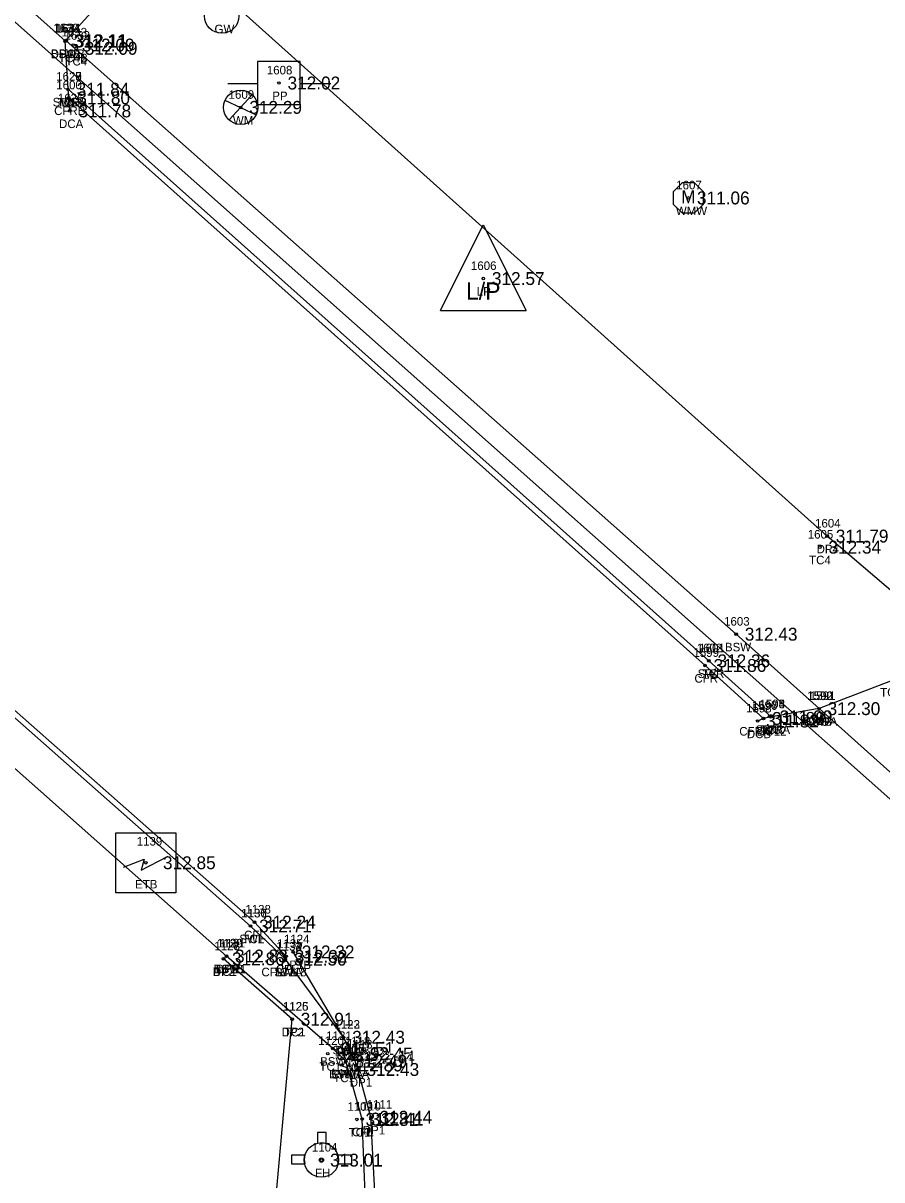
# Model space of a CAD drawing. Extents: x 1970076 to 1971136, y 803126 to 804215.
# Drawn here: x 1970842 to 1970942, y 803243.6 to 803378.3 of the extents above; entities that cross this region are included whole.
import ezdxf

# ---------------------------------------------------------------- set-up
doc = ezdxf.new("R2010")
doc.units = 0
for name, color, linetype in [('RD_EX_Conc', 7, 'Continuous'), ('RD_EX_Conc_txCode', 7, 'Continuous'), ('RD_EX_DR_Pipe', 7, 'Continuous'), ('RD_EX_Driveway', 7, 'Continuous'), ('RD_EX_Driveway_txCode', 7, 'Continuous'), ('RD_EX_Misc_txCode', 7, 'Continuous'), ('RD_EX_SU_H2O', 7, 'Continuous'), ('RD_EX_TX_Conc_ELEV', 7, 'Continuous'), ('RD_EX_TX_Driveway_ELEV', 7, 'Continuous'), ('RD_EX_TX_Misc_ELEV', 7, 'Continuous'), ('RD_EX_TX_UT_ELEV', 7, 'Continuous'), ('RD_EX_UT', 7, 'Continuous'), ('RD_EX_UT_txCode', 7, 'Continuous'), ('RD_HC_Survey_ELEV', 7, 'Continuous'), ('RD_SMD_Locator', 7, 'Continuous')]:
    doc.layers.add(name, color=color, linetype=linetype)

msp = doc.modelspace()

# ---------------------------------------------------------------- linework, layer by layer
at = {"layer": 'RD_EX_Conc'}
for points in [[(1970847.44, 803368.09), (1970847.23, 803370.61), (1970846.91, 803376.25), (1970825.43, 803395.36), (1970822.14, 803392.47), (1970821.14, 803392.59), (1970820.38, 803392.03)], [(1970934.65, 803298.46), (1970925.01, 803307.13), (1970847.03, 803376.25)], [(1970929.07, 803297.51), (1970921.83, 803304.03), (1970847.23, 803370.61)], [(1970928.19, 803297.32), (1970921.38, 803303.49), (1970847.31, 803369.61)], [(1970879.58, 803257.38), (1970880.21, 803258.23), (1970879.31, 803260.18), (1970872.53, 803269.28), (1970868.47, 803273.14), (1970819.57, 803316.35), (1970792.83, 803340.24), (1970791.56, 803341.26)], [(1970872.53, 803269.28), (1970872.62, 803269.6), (1970868.93, 803273.59), (1970819.97, 803316.84), (1970793.14, 803340.78), (1970791.95, 803341.72)], [(1970879.58, 803257.38), (1970878.06, 803258.86), (1970865.67, 803269.64), (1970816.24, 803313.45), (1970789.11, 803337.91)], [(1971009.74, 803224.24), (1971010.01, 803224.85), (1971010.25, 803225.52), (1971006.59, 803233.99), (1970934.65, 803298.46), (1970929.07, 803297.51), (1970928.19, 803297.32), (1970927.5, 803297.02)], [(1970854.49, 803199.55), (1970873.43, 803218.79), (1970878.63, 803227.37), (1970881.85, 803240.99), (1970881.47, 803250.65), (1970879.58, 803257.38)]]:
    msp.add_lwpolyline(points, dxfattribs=at)
at = {"layer": 'RD_EX_DR_Pipe'}
msp.add_line((1971022.85, 803216.85), (1970817.34, 803399.52), dxfattribs=at)
at = {"layer": 'RD_EX_Driveway'}
for points in [[(1970978.49, 803349.37), (1970974.36, 803344.54), (1970973.43, 803342.01), (1970974.82, 803339.34), (1970978.6, 803335.88), (1970962.13, 803321.3), (1970960.21, 803322.85), (1970957.7, 803323.38), (1970955.12, 803322.32), (1970943.79, 803311.55), (1970935.6, 803318.56), (1970864.97, 803381.97), (1970876.89, 803395.59), (1970878.3, 803398.67), (1970875.35, 803402.77), (1970871.74, 803402.91), (1970869.45, 803401.14), (1970846.9, 803376.22)], [(1970991.2, 803336.74), (1970966.5, 803314.66), (1970943.49, 803301.87), (1970934.65, 803298.46)], [(1970853.81, 803200.3), (1970867.75, 803214.13), (1970871.37, 803240.87), (1970873.32, 803262.28), (1970865.32, 803269.32), (1970865.67, 803269.64), (1970816.24, 803313.45)], [(1970855.26, 803198.86), (1970874.18, 803218.16), (1970879.6, 803226.99), (1970883.03, 803240.73), (1970882.49, 803250.86), (1970880.97, 803256.43), (1970880.48, 803257.86), (1970879.31, 803260.18), (1970873.44, 803270.12)]]:
    msp.add_lwpolyline(points, dxfattribs=at)
at = {"layer": 'RD_EX_SU_H2O'}
msp.add_lwpolyline([(1970921.19, 803357.22), (1970921.19, 803358.68), (1970920.16, 803359.7), (1970918.71, 803359.7), (1970917.68, 803358.68), (1970917.68, 803357.22), (1970918.71, 803356.2), (1970920.16, 803356.2)], close=True, dxfattribs=at)
at = {"layer": 'RD_EX_UT'}
for p, q in [((1970874.27, 803373.85), (1970869.27, 803373.85)), ((1970869.27, 803373.85), (1970869.27, 803368.85)), ((1970874.27, 803368.85), (1970874.27, 803373.85)), ((1970865.84, 803371.29), (1970869.31, 803371.29)), ((1970874.2, 803371.29), (1970877.84, 803371.29)), ((1970865.49, 803369.34), (1970869.13, 803367.63)), ((1970865.98, 803367.04), (1970868.64, 803369.94)), ((1970869.27, 803368.85), (1970874.27, 803368.85)), ((1970890.57, 803344.83), (1970895.57, 803354.83)), ((1970895.57, 803354.83), (1970900.57, 803344.83)), ((1970890.57, 803344.83), (1970900.57, 803344.83)), ((1970876.27, 803249.09), (1970876.27, 803247.82)), ((1970877.27, 803249.09), (1970876.27, 803249.09)), ((1970877.27, 803247.8), (1970877.27, 803249.09)), ((1970874.81, 803246.44), (1970873.25, 803246.44)), ((1970873.25, 803246.44), (1970873.25, 803245.44)), ((1970873.25, 803245.44), (1970874.77, 803245.44)), ((1970880.25, 803246.44), (1970878.64, 803246.44)), ((1970878.68, 803245.44), (1970880.25, 803245.44)), ((1970880.25, 803245.44), (1970880.25, 803246.44))]:
    msp.add_line(p, q, dxfattribs=at)
msp.add_lwpolyline([(1970852.78, 803277.01), (1970852.78, 803284.01), (1970859.78, 803284.01), (1970859.78, 803277.01)], close=True, dxfattribs=at)
msp.add_lwpolyline([(1970853.68, 803280.01), (1970856.1, 803280.91), (1970855.75, 803279.66), (1970858.8, 803281.25)], dxfattribs=at)
for centre, radius in [((1970865.13, 803379.13), 2), ((1970867.33, 803368.5), 2), ((1970876.73, 803245.87), 2), ((1970876.73, 803245.87), 0.25)]:
    msp.add_circle(centre, radius, dxfattribs=at)
for start, end in [(74.2455, 103.2128), (163.3387, 192.315), (347.685, 16.6613)]:
    msp.add_arc((1970876.73, 803245.87), 2, start, end, dxfattribs=at)
at = {"layer": 'RD_SMD_Locator'}
for centre in [(1970846.9, 803376.22), (1970846.91, 803376.25), (1970847.03, 803376.25), (1970847.84, 803375.76), (1970848.18, 803375.38), (1970847.23, 803370.61), (1970847.23, 803370.61), (1970847.23, 803370.61), (1970871.78, 803371.34), (1970847.31, 803369.61), (1970847.44, 803368.09), (1970867.33, 803368.5), (1970919.44, 803357.95), (1970895.57, 803348.56), (1970935.6, 803318.56), (1970934.75, 803317.27), (1970925.01, 803307.13), (1970921.38, 803303.49), (1970921.83, 803304.03), (1970921.83, 803304.03), (1970934.65, 803298.46), (1970934.65, 803298.46), (1970934.65, 803298.46), (1970927.5, 803297.02), (1970928.19, 803297.32), (1970928.19, 803297.32), (1970929.07, 803297.51), (1970929.07, 803297.51), (1970929.07, 803297.51), (1970856.28, 803280.51), (1970868.93, 803273.59), (1970868.47, 803273.14), (1970868.47, 803273.14), (1970865.32, 803269.32), (1970865.32, 803269.32), (1970865.67, 803269.64), (1970865.67, 803269.64), (1970865.67, 803269.64), (1970872.62, 803269.6), (1970873.44, 803270.12), (1970872.53, 803269.28), (1970872.53, 803269.28), (1970872.53, 803269.28), (1970873.32, 803262.28), (1970873.32, 803262.28), (1970879.31, 803260.18), (1970879.31, 803260.18), (1970878.06, 803258.86), (1970877.46, 803258.27), (1970879.58, 803257.38), (1970879.58, 803257.38), (1970879.58, 803257.38), (1970880.21, 803258.23), (1970880.48, 803257.86), (1970879.06, 803256.95), (1970880.97, 803256.43), (1970880.86, 803250.61), (1970881.47, 803250.65), (1970882.49, 803250.86), (1970876.73, 803245.87)]:
    msp.add_circle(centre, 0.15, dxfattribs=at)

# ---------------------------------------------------------------- texts
at = {"layer": 'RD_EX_Conc_txCode'}
for s, p in [('1630', (1970845.5, 803377.25)), ('1634', (1970845.66, 803377.25)), ('1633', (1970846.47, 803376.76)), ('1632', (1970846.81, 803376.38)), ('BSWB', (1970845.24, 803374.25)), ('TC4B', (1970846.12, 803373.76)), ('DC', (1970846.13, 803374.25)), ('TC4', (1970846.93, 803373.38)), ('1627', (1970845.85, 803371.61)), ('1628', (1970845.85, 803371.61)), ('1629', (1970845.85, 803371.61)), ('1600', (1970845.86, 803370.61)), ('SWRB', (1970845.44, 803368.61)), ('TCB', (1970845.96, 803368.61)), ('1626', (1970846.05, 803369.09)), ('DC', (1970846.45, 803368.61)), ('CFRB', (1970845.61, 803367.61)), ('DCA', (1970846.18, 803366.09)), ('1605', (1970933.34, 803318.27)), ('TC4', (1970933.5, 803315.27)), ('1603', (1970923.6, 803308.13)), ('1602', (1970920.42, 803305.03)), ('1601', (1970920.71, 803305.03)), ('BSW', (1970923.7, 803305.13)), ('1599', (1970920.03, 803304.49)), ('CFR', (1970920.15, 803301.49)), ('SWR', (1970920.52, 803302.03)), ('TC', (1970921.04, 803302.03)), ('1592', (1970933.31, 803299.46)), ('1591', (1970933.59, 803299.46)), ('TC2B', (1970941.77, 803299.87)), ('1596', (1970926.82, 803298.32)), ('1597', (1970926.85, 803298.32)), ('1593', (1970927.72, 803298.51)), ('1594', (1970927.72, 803298.51)), ('1595', (1970927.72, 803298.51)), ('1598', (1970926.16, 803298.02)), ('SWRA', (1970927.27, 803295.51)), ('TCA', (1970927.79, 803295.51)), ('DC', (1970928.29, 803295.51)), ('BSWA', (1970932.85, 803296.46)), ('DC', (1970933.87, 803296.46)), ('CFRA 12', (1970925.37, 803295.32)), ('DCB', (1970926.25, 803295.02)), ('DC', (1970927.41, 803295.32)), ('1136', (1970867.38, 803274.14)), ('1137', (1970867.4, 803274.14)), ('1138', (1970867.87, 803274.59)), ('SWL', (1970867.17, 803271.14)), ('TC1', (1970867.51, 803271.14)), ('CFL', (1970867.72, 803271.59)), ('1127', (1970864.26, 803270.32)), ('1130', (1970864.57, 803270.64)), ('1129', (1970864.61, 803270.64)), ('1132', (1970871.47, 803270.28)), ('1133', (1970871.47, 803270.28)), ('1134', (1970871.47, 803270.28)), ('1135', (1970871.56, 803270.6)), ('TC1B', (1970864.24, 803267.64)), ('BSW1', (1970864.19, 803267.64)), ('TC1', (1970864.36, 803267.32)), ('CFLA 18', (1970869.74, 803267.28)), ('TC1A', (1970871.08, 803267.28)), ('SWL', (1970871.24, 803267.28)), ('CFL', (1970871.42, 803267.6)), ('1125', (1970872.26, 803263.28)), ('1122', (1970878.24, 803261.18)), ('TC1', (1970872.36, 803260.28)), ('1120', (1970876.36, 803259.27)), ('1121', (1970877.28, 803259.86)), ('1118', (1970879.44, 803259.23)), ('SWL', (1970878.02, 803258.18)), ('1119', (1970878.28, 803257.95)), ('1116', (1970878.77, 803258.38)), ('1115', (1970878.8, 803258.38)), ('1117', (1970878.8, 803258.38)), ('BSW1', (1970876.58, 803256.86)), ('TC1', (1970876.5, 803256.27)), ('BSW1A', (1970877.61, 803255.38)), ('SWLA', (1970877.8, 803255.38)), ('CFLB', (1970877.9, 803255.38)), ('SWL', (1970878.92, 803256.23)), ('TC1', (1970878.1, 803254.95)), ('1109', (1970879.75, 803251.61)), ('1110', (1970880.66, 803251.65)), ('TC1', (1970879.9, 803248.61)), ('CFL', (1970880.27, 803248.65))]:
    msp.add_text(s, height=1, dxfattribs=at).set_placement(p)
at = {"layer": 'RD_EX_Driveway_txCode'}
for s, p in [('1631', (1970845.81, 803377.22)), ('DP4B', (1970845.2, 803374.22)), ('1604', (1970934.19, 803319.56)), ('DP4', (1970934.37, 803316.56)), ('1590', (1970933.27, 803299.46)), ('DPB', (1970933.4, 803296.46)), ('1124', (1970872.37, 803271.12)), ('1128', (1970864.26, 803270.32)), ('1131', (1970864.89, 803270.64)), ('DP2', (1970864.09, 803267.32)), ('DP2', (1970864.44, 803267.64)), ('DP1B', (1970872.02, 803268.12)), ('1126', (1970872.23, 803263.28)), ('1123', (1970878.24, 803261.18)), ('DP2', (1970872.09, 803260.28)), ('DP1', (1970878.36, 803258.18)), ('1113', (1970879.7, 803258.86)), ('1112', (1970880.19, 803257.43)), ('DP1', (1970879.53, 803255.86)), ('DP1', (1970880.03, 803254.43)), ('1111', (1970881.99, 803251.86)), ('DP1', (1970881.54, 803248.86))]:
    msp.add_text(s, height=1, dxfattribs=at).set_placement(p)
at = {"layer": 'RD_EX_Misc_txCode'}
for s, p in [('1607', (1970918.03, 803358.95)), ('WMW', (1970917.99, 803355.95))]:
    msp.add_text(s, height=1, dxfattribs=at).set_placement(p)
at = {"layer": 'RD_EX_SU_H2O'}
msp.add_text('M', height=1.5, dxfattribs=at).set_placement((1970918.6, 803357.34))
at = {"layer": 'RD_EX_TX_Conc_ELEV'}
for s, p in [('312.11', (1970847.91, 803375.5)), ('312.11', (1970848.03, 803375.5)), ('312.09', (1970848.84, 803375.01)), ('312.09', (1970849.18, 803374.63)), ('311.84', (1970848.23, 803369.86)), ('311.84', (1970848.23, 803369.86)), ('311.84', (1970848.23, 803369.86)), ('311.80', (1970848.31, 803368.86)), ('311.78', (1970848.44, 803367.34)), ('312.34', (1970935.75, 803316.52)), ('312.43', (1970926.01, 803306.38)), ('312.36', (1970922.83, 803303.28)), ('312.36', (1970922.83, 803303.28)), ('311.86', (1970922.38, 803302.74)), ('312.30', (1970935.65, 803297.71)), ('312.30', (1970935.65, 803297.71)), ('311.82', (1970928.5, 803296.27)), ('311.88', (1970929.19, 803296.57)), ('311.88', (1970929.19, 803296.57)), ('311.99', (1970930.07, 803296.76)), ('311.99', (1970930.07, 803296.76)), ('311.99', (1970930.07, 803296.76)), ('312.71', (1970869.47, 803272.39)), ('312.71', (1970869.47, 803272.39)), ('312.24', (1970869.93, 803272.84)), ('312.86', (1970866.32, 803268.57)), ('312.83', (1970866.67, 803268.89)), ('312.83', (1970866.67, 803268.89)), ('312.50', (1970873.53, 803268.53)), ('312.50', (1970873.53, 803268.53)), ('312.50', (1970873.53, 803268.53)), ('312.32', (1970873.62, 803268.85)), ('312.91', (1970874.32, 803261.53)), ('312.43', (1970880.31, 803259.43)), ('312.92', (1970878.46, 803257.52)), ('312.51', (1970879.06, 803258.11)), ('312.45', (1970881.21, 803257.48)), ('312.89', (1970880.06, 803256.2)), ('312.49', (1970880.58, 803256.63)), ('312.49', (1970880.58, 803256.63)), ('312.49', (1970880.58, 803256.63)), ('312.81', (1970881.86, 803249.86)), ('312.41', (1970882.47, 803249.9))]:
    msp.add_text(s, height=1.5, dxfattribs=at).set_placement(p)
at = {"layer": 'RD_EX_TX_Driveway_ELEV'}
for s, p in [('312.11', (1970847.9, 803375.47)), ('311.79', (1970936.6, 803317.81)), ('312.30', (1970935.65, 803297.71)), ('312.32', (1970874.44, 803269.37)), ('312.86', (1970866.32, 803268.57)), ('312.83', (1970866.67, 803268.89)), ('312.91', (1970874.32, 803261.53)), ('312.43', (1970880.31, 803259.43)), ('312.44', (1970881.48, 803257.11)), ('312.43', (1970881.97, 803255.68)), ('312.44', (1970883.49, 803250.11))]:
    msp.add_text(s, height=1.5, dxfattribs=at).set_placement(p)
at = {"layer": 'RD_EX_TX_Misc_ELEV'}
msp.add_text('311.06', height=1.5, dxfattribs=at).set_placement((1970920.44, 803357.2))
at = {"layer": 'RD_EX_TX_UT_ELEV'}
for s, p in [('312.29', (1970868.33, 803367.75)), ('312.57', (1970896.57, 803347.81)), ('312.85', (1970858.28, 803279.76)), ('313.01', (1970877.73, 803245.12))]:
    msp.add_text(s, height=1.5, dxfattribs=at).set_placement(p)
at = {"layer": 'RD_EX_UT'}
msp.add_text('L/P', height=2, dxfattribs=at).set_placement((1970893.56, 803346.11))
at = {"layer": 'RD_EX_UT_txCode'}
for s, p in [('GW', (1970864.28, 803377.13)), ('1608', (1970870.37, 803372.34)), ('1609', (1970865.92, 803369.5)), ('PP', (1970871, 803369.34)), ('WM', (1970866.42, 803366.5)), ('1606', (1970894.13, 803349.56)), ('LP', (1970894.81, 803346.56)), ('1139', (1970855.22, 803282.51)), ('ETB', (1970855.04, 803277.51)), ('1104', (1970875.62, 803246.87)), ('FH', (1970875.99, 803243.87))]:
    msp.add_text(s, height=1, dxfattribs=at).set_placement(p)
at = {"layer": 'RD_HC_Survey_ELEV'}
msp.add_text('312.02', height=1.5, dxfattribs=at).set_placement((1970872.78, 803370.59))

doc.saveas('drawing.dxf')
